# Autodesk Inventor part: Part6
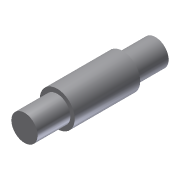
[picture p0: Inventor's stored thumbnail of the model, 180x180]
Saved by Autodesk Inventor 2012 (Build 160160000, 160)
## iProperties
Shininess: 77.0
Length Units: 11269
Angle Units: 11279
Time Units: 11290
Mass Units: 11283
Length Display Precision: 3
Angle Display Precision: 2
Created: 2002-01
Part Number: Part6
Document SubType Name: Modeling
Designer: ***
Density: 1 g/cm^3
Material: Default
Density: 0.0
Volumn: 0.0
Area: 0.0
PropertySet Name: Model Information
Control State: 0
Master: False
Checked Out: False
Author: ***
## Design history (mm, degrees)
sketch "Sketch1"
  geometry: L1 (1.545, 32.521)-(-4.455, 32.521); L2 (-4.455, 32.521)-(-4.455, 17.521); L3 (-4.455, 17.521)-(-6.455, 17.521); L4 (-6.455, 17.521)-(-6.455, -12.479); L5 (-6.455, -12.479)-(-4.455, -12.479); L6 (-4.455, -12.479)-(-4.455, -27.479); L7 (-4.455, -27.479)-(1.545, -27.479); L8 (1.545, -27.479)-(1.545, 32.521)
  constraints: 16 end point, 5 parallel, 2 equal length, 1 collinear, 1 horizontal, 1 perpendicular
  dimensions: "d0" = 16 diameter of L4 L8; "d1" = 12 diameter of L2 L8; "d2" = 60 distance of L7.end L1.start; "d3" = 30 distance of L3.end L4.end
revolve "Revolution1" sketch "Sketch1" stored, may be unused: angle "d4" = 90 deg
body "Solid1"
